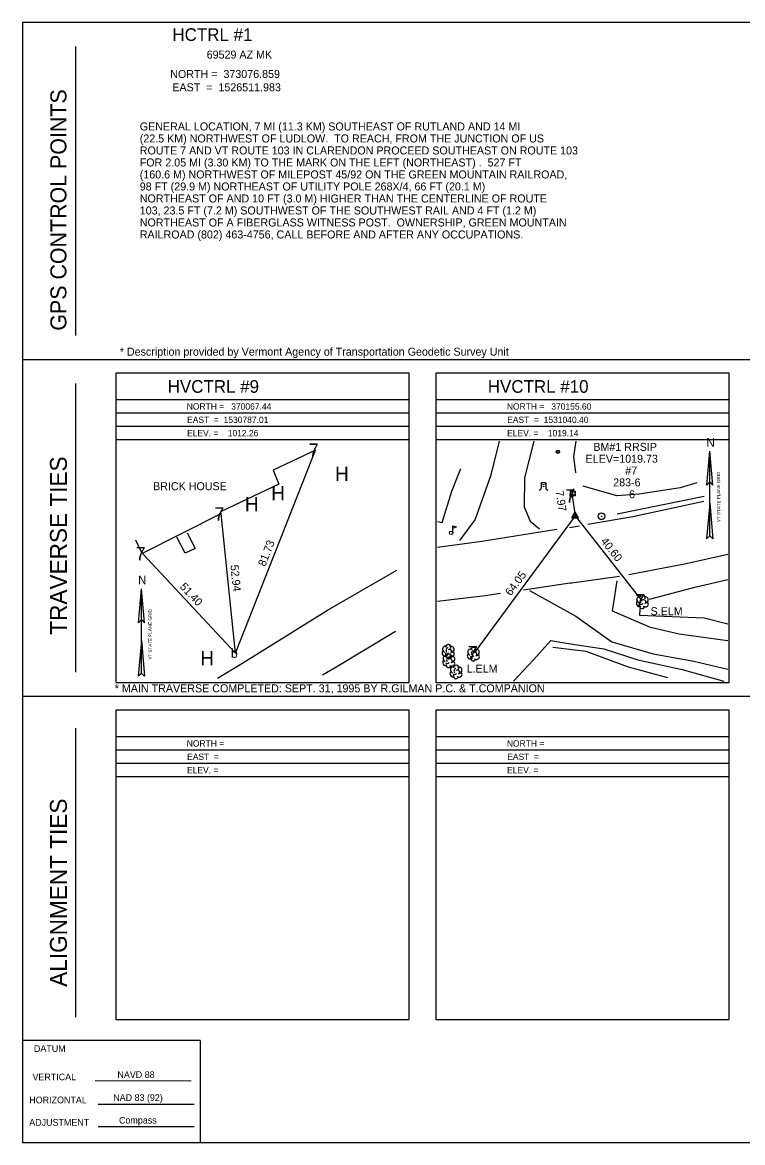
# Model space of a CAD drawing. Extents: x 1529965 to 1530605, y 369846 to 370266.
# Drawn here: x 1529965.3 to 1530235.3, y 369845.9 to 370265.9 of the extents above; entities that cross this region are included whole.
import ezdxf

# ---------------------------------------------------------------- set-up
doc = ezdxf.new("R2010")
doc.units = 0
for name, color, linetype in [('CPBM', 7, 'Continuous'), ('CPSM', 7, 'Continuous'), ('Default', 7, 'Continuous'), ('L_C', 7, 'Continuous'), ('LABL', 7, 'Continuous'), ('LAWA', 7, 'Continuous'), ('Level 1', 7, 'Continuous'), ('Level 11', 7, 'Continuous'), ('Level 12', 7, 'Continuous'), ('Level 13', 7, 'Continuous'), ('Level 14', 7, 'Continuous'), ('Level 43', 7, 'Continuous'), ('Level 44', 7, 'Continuous'), ('Level 45', 7, 'Continuous'), ('LFNC', 7, 'Continuous'), ('LMB', 7, 'Continuous'), ('LTD', 7, 'Continuous'), ('LTS', 7, 'Continuous'), ('NBL2', 7, 'Continuous'), ('PET', 7, 'Continuous'), ('PEU', 7, 'Continuous'), ('RDG', 7, 'Continuous'), ('RGP', 7, 'Continuous'), ('RGR', 7, 'Continuous'), ('U_C', 7, 'Continuous'), ('UP', 7, 'Continuous'), ('UPGW', 7, 'Continuous')]:
    doc.layers.add(name, color=color, linetype=linetype)

msp = doc.modelspace()

# ---------------------------------------------------------------- linework, layer by layer
at = {"layer": 'CPBM'}
for p, q in [((1530170.65, 370088.15), (1530170.65, 370089.15)), ((1530170.65, 370089.15), (1530171.65, 370089.15)), ((1530171.65, 370088.15), (1530170.65, 370088.15)), ((1530171.15, 370088.65), (1530171.15, 370088.65)), ((1530171.15, 370088.65), (1530171.15, 370088.65)), ((1530171.65, 370089.15), (1530171.65, 370088.15))]:
    msp.add_line(p, q, dxfattribs=at)
at = {"layer": 'CPSM'}
for p, q in [((1530171.29, 370080.08), (1530172.54, 370082.25)), ((1530171.29, 370080.08), (1530172.54, 370080.8)), ((1530171.29, 370080.08), (1530173.79, 370080.08)), ((1530173.79, 370080.08), (1530172.54, 370082.25)), ((1530172.54, 370080.8), (1530172.54, 370082.25)), ((1530172.54, 370080.8), (1530172.54, 370080.8)), ((1530172.54, 370080.8), (1530173.79, 370080.08))]:
    msp.add_line(p, q, dxfattribs=at)
at = {"layer": 'LABL'}
for points in [[(1530172.72, 370097.02), (1530172.06, 370103.08), (1530172.91, 370108.8)], [(1530218.2, 370093.19), (1530211.89, 370091.3), (1530196.48, 370089.02), (1530188.14, 370088.37), (1530175.55, 370092)]]:
    msp.add_lwpolyline(points, dxfattribs=at)
at = {"layer": 'LAWA'}
for points in [[(1530200.44, 370049.55), (1530217.88, 370054.24), (1530229.8, 370057.03)], [(1530229.8, 370040.18), (1530220.95, 370042.51), (1530196.78, 370043.47), (1530196.84, 370046.07)], [(1530149.46, 370018.91), (1530156.89, 370026.82), (1530163.4, 370034.1), (1530170.82, 370032.89), (1530183.25, 370031.02), (1530195.97, 370026.82), (1530212.66, 370023.19), (1530228.23, 370018.91)]]:
    msp.add_lwpolyline(points, dxfattribs=at)
at = {"layer": 'Level 1'}
for p, q in [((1530221.85, 370092.31), (1530222.99, 370105.08)), ((1530222.99, 370073.32), (1530222.99, 370105.08)), ((1530224.13, 370092.31), (1530222.99, 370105.08)), ((1530221.85, 370092.31), (1530222.99, 370093.56)), ((1530224.13, 370092.31), (1530222.99, 370093.56)), ((1530223, 370085.66), (1530221.81, 370072.27)), ((1530222.99, 370085.66), (1530224.18, 370072.27)), ((1530222.99, 370073.32), (1530221.81, 370072.27)), ((1530222.99, 370073.32), (1530224.18, 370072.27)), ((1530008.76, 370040.76), (1530009.9, 370053.53)), ((1530009.9, 370021.77), (1530009.9, 370053.53)), ((1530011.04, 370040.76), (1530009.9, 370053.53)), ((1530008.76, 370040.76), (1530009.9, 370042.02)), ((1530011.04, 370040.76), (1530009.9, 370042.02)), ((1530009.91, 370034.11), (1530008.72, 370020.73)), ((1530009.9, 370034.11), (1530011.08, 370020.73)), ((1530009.9, 370021.77), (1530008.72, 370020.73)), ((1530009.9, 370021.77), (1530011.08, 370020.73))]:
    msp.add_line(p, q, dxfattribs=at)
at = {"layer": 'Level 11'}
for p, q in [((1530079.7, 370045.46), (1530105.65, 370060.52)), ((1530047.54, 370025.5), (1530079.7, 370045.46)), ((1530105.18, 370037.5), (1530083.17, 370024.29)), ((1530038.41, 370020.03), (1530047.54, 370025.5)), ((1530083.17, 370024.29), (1530077.74, 370021.13))]:
    msp.add_line(p, q, dxfattribs=at)
at = {"layer": 'Level 12'}
for p, q in [((1530026.31, 370066.89), (1530023.24, 370072.91)), ((1530027.11, 370074.49), (1530030.01, 370068.58)), ((1530030.01, 370068.58), (1530026.31, 370066.89))]:
    msp.add_line(p, q, dxfattribs=at)
at = {"layer": 'Level 13'}
for p, q in [((1530075.12, 370105.43), (1530059.32, 370097.96)), ((1530059.32, 370097.96), (1530061.42, 370092.75)), ((1530061.42, 370092.75), (1530039.61, 370082.29)), ((1530039.71, 370081.56), (1530010.21, 370066.71)), ((1530039.61, 370082.29), (1530039.71, 370081.56)), ((1530010.21, 370066.71), (1530007.77, 370071.67))]:
    msp.add_line(p, q, dxfattribs=at)
at = {"layer": 'Level 43'}
for p, q in [((1530045.2, 370029.31), (1530075.16, 370105.49)), ((1530045.2, 370029.31), (1530039.76, 370081.54)), ((1530172.54, 370080.8), (1530134.81, 370029.57)), ((1530045.2, 370029.31), (1530010.27, 370066.7))]:
    msp.add_line(p, q, dxfattribs=at)
msp.add_lwpolyline([(1530171.39, 370088.33), (1530172.54, 370080.8), (1530197.47, 370048.99)], dxfattribs=at)
at = {"layer": 'LFNC'}
msp.add_lwpolyline([(1530120.97, 370078.75), (1530122.62, 370078.37), (1530126.26, 370090.1), (1530129.68, 370098.57)], dxfattribs=at)
at = {"layer": 'LMB'}
for p, q in [((1530126.71, 370077.08), (1530128.01, 370076.69)), ((1530126.72, 370074.48), (1530126.72, 370077.08)), ((1530126.72, 370076.18), (1530128, 370076.69)), ((1530126.06, 370074.48), (1530126.06, 370074.48))]:
    msp.add_line(p, q, dxfattribs=at)
msp.add_circle((1530126.06, 370074.48), 0.656, dxfattribs=at)
at = {"layer": 'LTD'}
for p, q in [((1530197.69, 370048.71), (1530197.69, 370048.71)), ((1530197.69, 370048.71), (1530197.69, 370048.71)), ((1530124.88, 370030.13), (1530124.88, 370030.13)), ((1530124.88, 370030.13), (1530124.88, 370030.13)), ((1530134.33, 370029.03), (1530134.33, 370029.03)), ((1530134.33, 370029.03), (1530134.33, 370029.03)), ((1530125.1, 370026.54), (1530125.1, 370026.54)), ((1530125.1, 370026.54), (1530125.1, 370026.54)), ((1530127.83, 370022.38), (1530127.83, 370022.38)), ((1530127.83, 370022.38), (1530127.83, 370022.38))]:
    msp.add_line(p, q, dxfattribs=at)
for centre in [(1530197.74, 370050.14), (1530124.92, 370031.57), (1530125.14, 370027.98), (1530134.37, 370030.46), (1530127.87, 370023.82)]:
    msp.add_arc(centre, 1.05, 335.5272, 180.9563, dxfattribs=at)
for centre, major_axis, ratio, start_param, end_param in [((1530196.9, 370049.38), (1.21, -0.51), 0.895232, 1.570796, 4.712389), ((1530197.48, 370049.17), (-0.208, -0.792), 0.645439, 3.141593, 6.283185), ((1530198.19, 370048.54), (-0.5, 0.667), 0.989748, 3.141593, 6.283185), ((1530198.73, 370049.29), (-1.14, -0.48), 0.949671, 1.570796, 4.712389), ((1530196.61, 370048), (0.58, -1.04), 0.959034, 3.141593, 6.283185), ((1530197.69, 370047.21), (0.26, 1.06), 0.942809, 1.570796, 4.712389), ((1530197.23, 370047.96), (-0.625, -0.083), 0.423636, 0, 3.141593), ((1530198.69, 370047.88), (-1.09, 0.79), 0.841452, 1.570796, 4.712389), ((1530123.79, 370029.42), (0.58, -1.04), 0.959034, 3.141593, 6.283185), ((1530124.08, 370030.8), (1.21, -0.51), 0.895232, 1.570796, 4.712389), ((1530124.3, 370027.21), (1.21, -0.51), 0.895232, 1.570796, 4.712389), ((1530124.88, 370028.63), (0.26, 1.06), 0.942809, 1.570796, 4.712389), ((1530124.42, 370029.38), (-0.625, -0.083), 0.423636, 0, 3.141593), ((1530124.67, 370030.59), (-0.208, -0.792), 0.645439, 3.141593, 6.283185), ((1530125.38, 370029.97), (-0.5, 0.667), 0.989748, 3.141593, 6.283185), ((1530125.88, 370029.3), (-1.09, 0.79), 0.841452, 1.570796, 4.712389), ((1530125.92, 370030.72), (-1.14, -0.48), 0.949671, 1.570796, 4.712389), ((1530126.14, 370027.12), (-1.14, -0.48), 0.949671, 1.570796, 4.712389), ((1530133.24, 370028.32), (0.58, -1.04), 0.959034, 3.141593, 6.283185), ((1530133.53, 370029.69), (1.21, -0.51), 0.895232, 1.570796, 4.712389), ((1530134.12, 370029.48), (-0.208, -0.792), 0.645439, 3.141593, 6.283185), ((1530134.83, 370028.86), (-0.5, 0.667), 0.989748, 3.141593, 6.283185), ((1530135.33, 370028.19), (-1.09, 0.79), 0.841452, 1.570796, 4.712389), ((1530135.37, 370029.61), (-1.14, -0.48), 0.949671, 1.570796, 4.712389), ((1530124.01, 370025.83), (0.58, -1.04), 0.959034, 3.141593, 6.283185), ((1530125.1, 370025.04), (0.26, 1.06), 0.942809, 1.570796, 4.712389), ((1530124.64, 370025.79), (-0.625, -0.083), 0.423636, 0, 3.141593), ((1530124.89, 370027), (-0.208, -0.792), 0.645439, 3.141593, 6.283185), ((1530125.6, 370026.37), (-0.5, 0.667), 0.989748, 3.141593, 6.283185), ((1530126.1, 370025.71), (-1.09, 0.79), 0.841452, 1.570796, 4.712389), ((1530127.04, 370023.05), (1.21, -0.51), 0.895232, 1.570796, 4.712389), ((1530128.87, 370022.96), (-1.14, -0.48), 0.949671, 1.570796, 4.712389), ((1530134.33, 370027.53), (0.26, 1.06), 0.942809, 1.570796, 4.712389), ((1530133.87, 370028.28), (-0.625, -0.083), 0.423636, 0, 3.141593), ((1530126.74, 370021.67), (0.58, -1.04), 0.959034, 3.141593, 6.283185), ((1530127.83, 370020.88), (0.26, 1.06), 0.942809, 1.570796, 4.712389), ((1530127.37, 370021.63), (-0.625, -0.083), 0.423636, 0, 3.141593), ((1530127.62, 370022.84), (-0.208, -0.792), 0.645439, 3.141593, 6.283185), ((1530128.33, 370022.21), (-0.5, 0.667), 0.989748, 3.141593, 6.283185), ((1530128.83, 370021.55), (-1.09, 0.79), 0.841452, 1.570796, 4.712389)]:
    msp.add_ellipse(centre, major_axis=major_axis, ratio=ratio, start_param=start_param, end_param=end_param, dxfattribs=at)
at = {"layer": 'LTS'}
for p, q in [((1530159.83, 370093), (1530159.83, 370091.33)), ((1530160.66, 370091.86), (1530160.66, 370091.86)), ((1530160.66, 370091.86), (1530160.66, 370091.86)), ((1530160.66, 370091.83), (1530160.66, 370091.83)), ((1530161.5, 370092.83), (1530161.5, 370093)), ((1530161.5, 370093), (1530161.5, 370091.33))]:
    msp.add_line(p, q, dxfattribs=at)
msp.add_circle((1530160.66, 370091.86), 0.0833, dxfattribs=at)
for centre, start, end in [((1530159, 370091.33), 270, 360), ((1530162.33, 370091.33), 180, 270)]:
    msp.add_arc(centre, 0.833, start, end, dxfattribs=at)
msp.add_ellipse((1530160.66, 370093), major_axis=(-0.833, 0), ratio=0.5, dxfattribs=at)
at = {"layer": 'NBL2'}
for p, q in [((1529985.29, 370148.52), (1529985.29, 370256.85)), ((1529965.29, 370139.52), (1530605.29, 370139.52)), ((1529985.29, 370022.19), (1529985.29, 370130.52)), ((1530110.29, 370124.35), (1530000.29, 370124.35)), ((1530230.29, 370124.35), (1530120.29, 370124.35)), ((1530110.29, 370119.35), (1530000.29, 370119.35)), ((1530230.29, 370119.35), (1530120.29, 370119.35)), ((1530110.29, 370114.35), (1530000.29, 370114.35)), ((1530230.29, 370114.35), (1530120.29, 370114.35)), ((1530110.29, 370109.35), (1530000.29, 370109.35)), ((1530230.29, 370109.35), (1530120.29, 370109.35)), ((1529965.29, 370013.19), (1530605.29, 370013.19)), ((1529985.29, 369892.85), (1529985.29, 370001.19)), ((1530110.29, 369998.02), (1530000.29, 369998.02)), ((1530230.29, 369998.02), (1530120.29, 369998.02)), ((1530110.29, 369993.02), (1530000.29, 369993.02)), ((1530230.29, 369993.02), (1530120.29, 369993.02)), ((1530110.29, 369988.02), (1530000.29, 369988.02)), ((1530230.29, 369988.02), (1530120.29, 369988.02)), ((1530110.29, 369983.02), (1530000.29, 369983.02)), ((1530230.29, 369983.02), (1530120.29, 369983.02)), ((1530031.96, 369884.1), (1529965.29, 369884.1)), ((1530031.96, 369884.1), (1530031.96, 369845.85)), ((1530031.96, 369884.1), (1530031.96, 369845.85)), ((1529992.53, 369869.08), (1530028.53, 369869.05)), ((1529993.64, 369860.31), (1530029.64, 369860.31)), ((1529993.64, 369851.87), (1530029.64, 369851.84))]:
    msp.add_line(p, q, dxfattribs=at)
for points in [[(1529965.29, 369845.85), (1530605.29, 369845.85), (1530605.29, 370265.85), (1529965.29, 370265.85)], [(1530000.29, 370018.35), (1530110.29, 370018.35), (1530110.29, 370134.35), (1530000.29, 370134.35)], [(1530120.29, 370018.35), (1530230.29, 370018.35), (1530230.29, 370134.35), (1530120.29, 370134.35)], [(1530000.29, 369892.02), (1530110.29, 369892.02), (1530110.29, 370008.02), (1530000.29, 370008.02)], [(1530120.29, 369892.02), (1530230.29, 369892.02), (1530230.29, 370008.02), (1530120.29, 370008.02)]]:
    msp.add_lwpolyline(points, close=True, dxfattribs=at)
at = {"layer": 'PET'}
for points in [[(1530177.28, 370077.69), (1530194.12, 370080.64), (1530220.81, 370086.34)], [(1530120.97, 370069.04), (1530137.58, 370071.29), (1530165.69, 370075.9)], [(1530170.43, 370076.48), (1530174.11, 370077.13)], [(1530229.8, 370066.37), (1530214.11, 370062.82), (1530192.66, 370058.79)], [(1530189.2, 370058.14), (1530171.3, 370055.65)], [(1530170.58, 370055.59), (1530153.11, 370053)], [(1530171.3, 370055.65), (1530170.58, 370055.59)], [(1530144.54, 370051.74), (1530138.74, 370050.88), (1530120.97, 370048.67)]]:
    msp.add_lwpolyline(points, dxfattribs=at)
at = {"layer": 'PEU'}
for points in [[(1530229.8, 370033.95), (1530229.6, 370033.99), (1530211.46, 370036.53), (1530200.82, 370038.95), (1530186.48, 370045.14), (1530188.23, 370056.52)], [(1530155.43, 370052.91), (1530172.82, 370043.21), (1530186.24, 370033.64), (1530201.74, 370029.15), (1530217.06, 370026.37), (1530229.8, 370023.34)]]:
    msp.add_lwpolyline(points, dxfattribs=at)
at = {"layer": 'RDG'}
for points in [[(1530129.33, 370071.64), (1530135.09, 370079.32), (1530141, 370096.24), (1530144.16, 370108.8)], [(1530157.03, 370108.8), (1530153.53, 370095.04), (1530153.36, 370084.2), (1530155.71, 370078.9), (1530159.18, 370075.96)]]:
    msp.add_lwpolyline(points, dxfattribs=at)
at = {"layer": 'RGP'}
msp.add_line((1530182.41, 370080.68), (1530182.41, 370080.68), dxfattribs=at)
for radius in [1.25, 0.0833]:
    msp.add_circle((1530182.41, 370080.68), radius, dxfattribs=at)
at = {"layer": 'RGR'}
for points in [[(1530220.89, 370088.12), (1530188.22, 370081.47)], [(1530207.22, 370020.07), (1530192.46, 370024.17), (1530176.63, 370029.97), (1530164.13, 370031.47)]]:
    msp.add_lwpolyline(points, dxfattribs=at)
at = {"layer": 'UP'}
for p, q in [((1530170.82, 370088.41), (1530170.82, 370090.08)), ((1530170.82, 370090.08), (1530172.48, 370090.08)), ((1530172.48, 370088.41), (1530170.82, 370088.41)), ((1530171.4, 370087.58), (1530171.65, 370088.41)), ((1530171.9, 370090.91), (1530171.65, 370090.08)), ((1530171.65, 370089.24), (1530171.65, 370089.24)), ((1530172.48, 370090.08), (1530172.48, 370088.41))]:
    msp.add_line(p, q, dxfattribs=at)
msp.add_circle((1530171.65, 370089.24), 0.833, dxfattribs=at)
at = {"layer": 'UPGW'}
for radius in [0.625, 0.0833]:
    msp.add_circle((1530166.04, 370104.87), radius, dxfattribs=at)

# ---------------------------------------------------------------- texts
at = {"layer": 'Default'}
for s, rotation, p in [('7.97', 278.7063, (1530165.16, 370090.04)), ('81.73', 68.5331, (1530056.3, 370061.63)), ('40.60', 308.0838, (1530181.92, 370071.27)), ('52.94', 275.9446, (1530043.27, 370062.33)), ('64.05', 53.6355, (1530148.44, 370050.61)), ('51.40', 313.0469, (1530024.11, 370054.09))]:
    msp.add_text(s, height=3, rotation=rotation, dxfattribs=at).set_placement(p)
at = {"layer": 'L_C'}
for s, p in [('S.ELM', (1530200.8, 370043.58)), ('L.ELM', (1530131.85, 370022.03))]:
    msp.add_text(s, height=3, dxfattribs=at).set_placement(p)
at = {"layer": 'Level 1'}
for s, height, p in [('* Description provided by Vermont Agency of Transportation Geodetic Survey Unit', 3, (1530001.8, 370140.91)), ('N', 3.24, (1530221.74, 370106.74)), ('7', 5, (1530072.66, 370102.99)), ('7', 5, (1530168.89, 370085.83)), ('7', 5, (1530037.26, 370079.04)), ('7', 5, (1530007.77, 370064.2)), ('N', 3.24, (1530008.65, 370055.19)), ('7', 5, (1530194.97, 370046.49)), ('b', 3.4, (1530043.5, 370027.61)), ('7', 5, (1530132.31, 370027.07))]:
    msp.add_text(s, height=height, dxfattribs=at).set_placement(p)
for p in [(1530226.89, 370078.48), (1530013.8, 370026.93)]:
    msp.add_text('VT STATE PLANE GRID', height=1.2303, rotation=90.0204, dxfattribs=at).set_placement(p)
at = {"layer": 'Level 14'}
for p in [(1530082.53, 370093.97), (1530058.57, 370086.69), (1530048.72, 370082.56), (1530032.02, 370024.84)]:
    msp.add_text('H', height=5.3, dxfattribs=at).set_placement(p)
at = {"layer": 'Level 44'}
msp.add_text('BRICK HOUSE', height=3, dxfattribs=at).set_placement((1530014.28, 370090.46))
at = {"layer": 'Level 45'}
for s, p in [('GENERAL LOCATION, 7 MI (11.3 KM) SOUTHEAST OF RUTLAND AND 14 MI         ', (1530009.29, 370225.34)), ('(22.5 KM) NORTHWEST OF LUDLOW.  TO REACH, FROM THE JUNCTION OF US       ', (1530009.29, 370220.84)), ('ROUTE 7 AND VT ROUTE 103 IN CLARENDON PROCEED SOUTHEAST ON ROUTE 103    ', (1530009.29, 370216.34)), ('FOR 2.05 MI (3.30 KM) TO THE MARK ON THE LEFT (NORTHEAST) .  527 FT     ', (1530009.29, 370211.84)), ('(160.6 M) NORTHWEST OF MILEPOST 45/92 ON THE GREEN MOUNTAIN RAILROAD,   ', (1530009.29, 370207.34)), ('98 FT (29.9 M) NORTHEAST OF UTILITY POLE 268X/4, 66 FT (20.1 M)         ', (1530009.29, 370202.84)), ('NORTHEAST OF AND 10 FT (3.0 M) HIGHER THAN THE CENTERLINE OF ROUTE      ', (1530009.29, 370198.34)), ('103, 23.5 FT (7.2 M) SOUTHWEST OF THE SOUTHWEST RAIL AND 4 FT (1.2 M)   ', (1530009.29, 370193.84)), ('NORTHEAST OF A FIBERGLASS WITNESS POST.  OWNERSHIP, GREEN MOUNTAIN      ', (1530009.29, 370189.34)), ('RAILROAD (802) 463-4756, CALL BEFORE AND AFTER ANY OCCUPATIONS.   ', (1530009.29, 370184.84)), ('* MAIN TRAVERSE COMPLETED: SEPT. 31, 1995 BY R.GILMAN P.C. & T.COMPANION', (1529999.91, 370014.68))]:
    msp.add_text(s, height=3, dxfattribs=at).set_placement(p)
at = {"layer": 'NBL2'}
for s, height, p in [('      HCTRL #1     ', 4.75, (1530010.94, 370258.91)), (' 69529 AZ MK', 3, (1530033.27, 370252.28)), ('NORTH =  373076.859 ', 3, (1530020.71, 370245.02)), ('EAST  =  1526511.983', 3, (1530021.5, 370240.02)), ('     HVCTRL #9     ', 4.75, (1530010.94, 370126.98)), ('     HVCTRL #10    ', 4.75, (1530130.94, 370126.98)), ('NORTH =   370067.44 ', 2.375, (1530026.91, 370120.67)), ('NORTH =   370155.60 ', 2.375, (1530146.91, 370120.67)), ('EAST  =  1530787.01 ', 2.375, (1530027.05, 370115.67)), ('EAST  =  1531040.40 ', 2.375, (1530147.05, 370115.67)), ('ELEV. =    1012.26  ', 2.375, (1530027.02, 370110.67)), ('ELEV. =    1019.14  ', 2.375, (1530147.02, 370110.67)), ('NORTH =             ', 2.375, (1530026.91, 369994.33)), ('NORTH =             ', 2.375, (1530146.91, 369994.33)), ('EAST  =             ', 2.375, (1530027.05, 369989.33)), ('EAST  =             ', 2.375, (1530147.05, 369989.33)), ('ELEV. =             ', 2.375, (1530027.02, 369984.33)), ('ELEV. =             ', 2.375, (1530147.02, 369984.33)), ('DATUM', 2.5, (1529969.61, 369879.87)), ('  NAVD 88 ', 2.5, (1529999.06, 369870.09)), ('HORIZONTAL', 2.5, (1529967.87, 369860.6)), ('NAD 83 (92)', 2.5, (1529999.35, 369861.48)), ('ADJUSTMENT', 2.5, (1529967.87, 369852.17)), ('  Compass ', 2.5, (1529999.66, 369852.99))]:
    msp.add_text(s, height=height, dxfattribs=at).set_placement(p)
for s, height, rotation, p in [('GPS CONTROL POINTS', 6, 90, (1529981.79, 370150.27)), ('TRAVERSE TIES', 6.3332, 90, (1529981.96, 370036.29)), ('ALIGNMENT TIES', 6.3332, 90, (1529981.96, 369904.26)), ('VERTICAL', 2.5, 0.1439, (1529969.07, 369869.2))]:
    msp.add_text(s, height=height, rotation=rotation, dxfattribs=at).set_placement(p)
at = {"layer": 'U_C'}
for s, p in [('BM#1 RRSIP', (1530179.33, 370105.2)), ('ELEV=1019.73', (1530176.44, 370100.76)), ('#7', (1530191.32, 370096.32)), ('283-6', (1530186.77, 370091.88)), ('6', (1530192.73, 370087.43))]:
    msp.add_text(s, height=3, dxfattribs=at).set_placement(p)

doc.saveas('drawing.dxf')
